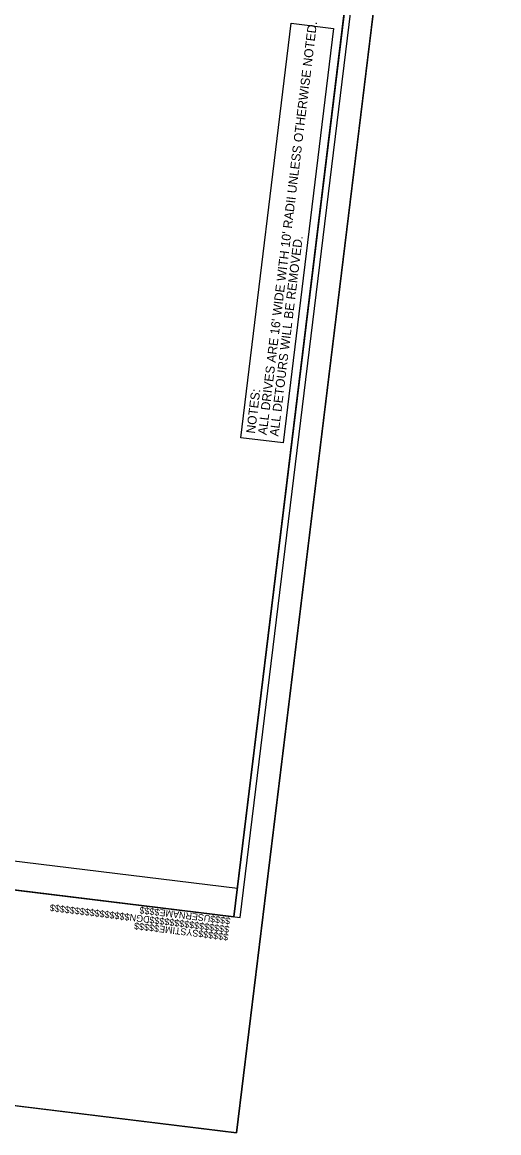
# Model space of a CAD drawing. Extents: x 480344 to 482186, y 488805 to 491553.
# Drawn here: x 481536 to 481907, y 488805 to 489669 of the extents above; entities that cross this region are included whole.
import ezdxf

# ---------------------------------------------------------------- set-up
doc = ezdxf.new("R2010")
doc.units = 0
for name, color, linetype in [('Prop DSN Text', 7, 'Continuous'), ('Prop Grid Mask', 7, 'Continuous'), ('Sheet Cutting Line CELL', 7, 'Continuous'), ('Sheet Layout Plan Border', 7, 'Continuous'), ('Sheet Plan CELL', 7, 'Continuous'), ('Sheet Plan Layout CELL', 7, 'Continuous'), ('Sheet Plot Border Inside CELL', 7, 'Continuous'), ('Sheet Plot Border Outside CELL', 7, 'Continuous')]:
    doc.layers.add(name, color=color, linetype=linetype)

msp = doc.modelspace()

# ---------------------------------------------------------------- linework, layer by layer
at = {"layer": 'Prop Grid Mask'}
msp.add_lwpolyline([(481705.83, 489345.51), (481745.2, 489667.9), (481778.17, 489663.88), (481738.8, 489341.48)], close=True, dxfattribs=at)
at = {"layer": 'Sheet Cutting Line CELL'}
for p, q in [((481702.68, 488805.07), (481906.78, 490476.15)), ((480615.75, 488937.82), (481702.68, 488805.07))]:
    msp.add_line(p, q, dxfattribs=at)
at = {"layer": 'Sheet Layout Plan Border'}
msp.add_lwpolyline([(481703.23, 488995.25), (481861.69, 490292.69), (481782.27, 490302.39), (481802.94, 490471.69), (481574.79, 490460.72), (481089.79, 490519.96), (481007.71, 490529.98), (480988.13, 490369.7), (480815.85, 490390.73), (480660.97, 489122.55)], close=True, dxfattribs=at)
at = {"layer": 'Sheet Plan CELL'}
for p, q in [((481882.37, 490462), (481700.51, 488973.06)), ((481700.51, 488973.06), (480658.28, 489100.33)), ((481700.51, 488973.06), (481700.51, 488973.06))]:
    msp.add_line(p, q, dxfattribs=at)
msp.add_lwpolyline([(480840.12, 490589.33), (480658.26, 489100.35), (481700.51, 488973.06), (481882.37, 490462)], close=True, dxfattribs=at)
at = {"layer": 'Sheet Plan Layout CELL'}
for p, q in [((481700.51, 488973.06), (481882.37, 490461.99)), ((480658.28, 489100.33), (481700.51, 488973.06))]:
    msp.add_line(p, q, dxfattribs=at)
at = {"layer": 'Sheet Plot Border Inside CELL'}
msp.add_lwpolyline([(481705.46, 488972.43), (481887.32, 490461.41), (480840.14, 490589.31), (480658.28, 489100.33)], close=True, dxfattribs=at)
at = {"layer": 'Sheet Plot Border Outside CELL'}
msp.add_lwpolyline([(480615.75, 488937.82), (480819.86, 490608.9), (481906.78, 490476.15), (481702.68, 488805.07)], close=True, dxfattribs=at)

# ---------------------------------------------------------------- texts
at = {"layer": 'Prop DSN Text'}
for s, p in [("ALL DRIVES ARE 16' WIDE WITH 10' RADII UNLESS OTHERWISE NOTED. ", (481726.07, 489347.4)), ('ALL DETOURS WILL BE REMOVED. ', (481735.18, 489346.29)), ('NOTES: ', (481716.96, 489348.51))]:
    msp.add_text(s, height=7, rotation=83.03651, dxfattribs=at).set_placement(p)
at = {"layer": 'Sheet Plan CELL'}
for s, p in [('$$$$$$$$$$$$$$$$DGN$$$$$$$$$$$$$$$$', (481697.24, 488965.76)), ('$$$$USERNAME$$$$', (481698.03, 488972.26)), ('$$$$$$SYSTIME$$$$$', (481696.53, 488959.73))]:
    msp.add_text(s, height=5.25, rotation=173.03652, dxfattribs=at).set_placement(p)

doc.saveas('drawing.dxf')
